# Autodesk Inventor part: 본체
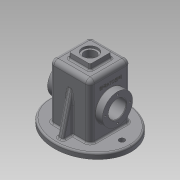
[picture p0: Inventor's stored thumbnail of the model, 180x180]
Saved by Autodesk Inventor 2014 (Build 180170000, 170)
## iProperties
Created: 2017-07
Part Number: 본체
Material: Generic
Document SubType Name: Modeling
Designer: user
Density: 1 g/cm^3
Appearance: Default
Author: user
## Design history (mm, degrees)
sketch "스케치1"
  geometry: 1 further point
sketch "스케치2"
  geometry: 1 further point
sketch "스케치3"
  geometry: 1 further point; 1 other entity
  constraints: 2 other
extrude "돌출1" new body sketch "스케치3" distance "d2" = 10; taper "d3" = 0 deg
sketch "스케치4"
  geometry: L1 (-37, -37)-(37, -37); L2 (37, -37)-(37, 37); L3 (37, 37)-(-37, 37); L4 (-37, 37)-(-37, -37); L5 (-37, -37)-(37, 37); L6 (37, -37)-(-37, 37); 1 further point; 1 other entity
  constraints: 12 end point, 2 midpoint, 2 parallel, 1 horizontal, 1 perpendicular, 1 other
  dimensions: "d4" = 74 distance of L3.end L2.end; "d5" = 74 distance of L2.end L1.end
extrude "돌출2" join sketch "스케치4" distance "d6" = 100; taper "d7" = 0 deg
fillet "모깎기1" dims "d8" = 8
fillet "모깎기2" dims "d9" = 8
sketch "스케치5"
  geometry: L1 (-32, -32)-(32, -32); L2 (32, -32)-(32, 32); L3 (32, 32)-(-32, 32); L4 (-32, 32)-(-32, -32); L5 (-32, -32)-(32, 32); L6 (32, -32)-(-32, 32); 1 further point; 1 other entity
  constraints: 12 end point, 2 midpoint, 2 parallel, 1 horizontal, 1 perpendicular, 1 other
  dimensions: "d10" = 64 distance of L3.end L2.end; "d11" = 64 distance of L2.end L1.end
extrude "돌출3" cut sketch "스케치5" distance "d12" = 105; taper "d13" = 0 deg
sketch "스케치6"
  geometry: L1 (-32, 0)-(32, 0) reference; L2 (-32, 0)-(-32, 105) reference; L3 (-32, 105)-(32, 105) reference; L4 (32, 0)-(32, 105) reference; L5 (75, 10)-(-75, 10) reference; L6 (-75, 0)-(75, 0) reference; L7 (-37, 102)-(-29, 102) reference; L8 (-37, 102)-(-37, 10) reference; L9 (-37, 10)-(-29, 10) reference; L10 (-29, 10)-(-29, 102) reference; L11 (-29, 110)-(-29, 102) reference; L12 (-29, 102)-(29, 102) reference; L13 (29, 102)-(29, 110) reference; L14 (29, 110)-(-29, 110) reference; L15 (29, 102)-(37, 102) reference; L16 (29, 102)-(29, 10) reference; L17 (29, 10)-(37, 10) reference; L18 (37, 10)-(37, 102) reference; L19 (-37, 10)-(-37, 55); L20 (-37, 82.5)-(-50, 82.5); L21 (-50, 82.5)-(-50, 71); L22 (-50, 71)-(-25, 71); L23 (-37, 82.5)-(-32, 82.5); L24 (-37, 55)-(-37, 71); L25 (-32, 82.5)-(-17, 82.5); L26 (-25, 71)-(-25, 75.5); L27 (-25, 75.5)-(-32, 82.5); L28 (-32, 0)-(-32, 105) reference; L29 (-37, 55)-(-17, 55); L30 (-37, 102)-(-37, 10) reference; L31 (-25, 71)-(-25, 75.5); L32 (-32, 82.5)-(-25, 75.5); L33 (-32, 82.5)-(-50, 82.5); L34 (-50, 82.5)-(-50, 71); L35 (-50, 71)-(-25, 71); 1 further point
  constraints: 30 end point, 6 perpendicular, 4 collinear, 4 point on line, 1 horizontal
  node "투영된 루프1"
  node "투영된 루프2"
  node "투영된 루프3"
  node "투영된 루프4"
  node "투영된 루프5"
revolve "회전1" stored, may be unused: angle "d22" = 90 deg
fillet "모깎기3" dims "d23" = 0.5
sketch "스케치7"
  geometry: C1 r 16 at (0, 0) reference; C2 r 16 at (0, 0) reference; 1 further point
extrude "돌출4" cut sketch "스케치7" distance "d24" = 20; taper "d25" = 0 deg
sketch "스케치8"
  geometry: L1 (0, 0)-(-22.5, 0); C1 r 27.5 at (0, 0) reference; 1 further point
  constraints: 2 end point, 1 horizontal
  dimensions: "d26" = 22.5 distance of L1.start L1.end
hole "구멍1" sketch "스케치8" at (-22.5, 0) diameter "d27" = 3.242; stored, may be unused: countersink angle "d31" = 90 deg, drill point angle "d33" = 118 deg; dims "d28" = 8, "d29" = 4, "d30" = 2, "d32" = 10
fillet "모깎기4" dims "d37" = 3
fillet "모깎기5" dims "d38" = 3
chamfer "모따기1" distance "d39" = 1; stored, may be unused: second distance "d40" = 2, angle "d41" = 45 deg
sketch "스케치9"
  geometry: C1 r 16 at (0, 0) reference; C2 r 16 at (0, 0) reference; 1 further point
extrude "돌출5" cut sketch "스케치9" distance "d42" = 20; taper "d43" = 0 deg
revolve "회전2" stored, may be unused: angle "d44" = 90 deg
sketch "스케치10"
  geometry: L1 (0, 0)-(-22.472, 0); C1 r 27.5 at (0, 0) reference; 1 further point
  constraints: 2 end point, 1 horizontal
hole "구멍2" sketch "스케치10" at (-22.472, 0) diameter "d46" = 3.242; stored, may be unused: countersink angle "d50" = 90 deg, drill point angle "d52" = 118 deg; dims "d47" = 8, "d48" = 4, "d49" = 2, "d51" = 10
fillet "모깎기6" dims "d56" = 0.5
fillet "모깎기7" dims "d57" = 0.5
fillet "모깎기8" dims "d58" = 3
fillet "모깎기9" dims "d59" = 3
sketch "스케치11"
  geometry: L1 (-20, -20)-(20, -20); L2 (20, -20)-(20, 20); L3 (20, 20)-(-20, 20); L4 (-20, 20)-(-20, -20); L5 (-20, -20)-(20, 20); L6 (20, -20)-(-20, 20); 1 further point
  constraints: 12 end point, 2 midpoint, 2 parallel, 1 horizontal, 1 perpendicular
  dimensions: "d60" = 40 distance of L3.end L2.end; "d61" = 40 distance of L2.end L1.end
extrude "돌출6" join sketch "스케치11" distance "d62" = 10; taper "d63" = -5 deg
fillet "모깎기10" dims "d64" = 3
fillet "모깎기11" dims "d65" = 3
sketch "스케치12"
  geometry: 1 further point
hole "구멍3" sketch "스케치12" at (0, 0) diameter "d66" = 21; stored, may be unused: countersink angle "d70" = 90 deg, drill point angle "d72" = 0 deg; dims "d67" = 8, "d68" = 28, "d69" = 4, "d71" = 20
sketch "스케치13"
  geometry: L1 (0, 0)-(58, 0); C1 r 5 at (58, 0); 1 other entity
  constraints: 2 end point, 1 centre point, 1 coincident, 1 horizontal, 1 other
  dimensions: "d73" = 58 distance of L1.start L1.end; "d74" = 10 diameter of C1
extrude "돌출7" cut sketch "스케치13" stored distance "d75" = 10; taper "d76" = 0 deg
fillet "모깎기12" dims "d77" = 3
sketch "스케치14"
  geometry: L1 (-37, 10)-(-37, 102) reference; L2 (-29, 102)-(-37, 102) reference; L3 (-29, 102)-(-29, 10) reference; L4 (-29, 10)-(-37, 10) reference; L5 (-37, 10)-(-37, 102) reference; L6 (29, 105)-(10.5, 105) reference; L7 (10.5, 105)-(10.5, 116) reference; L8 (10.5, 116)-(14, 116) reference; L9 (14, 116)-(14, 120) reference; L10 (14, 120)-(19.125, 120) reference; L11 (19.125, 120)-(19.76, 112.739) reference; L12 (22.749, 110)-(29, 110) reference; L13 (37, 102)-(37, 10) reference; L14 (37, 10)-(62, 10) reference; L15 (65, 7)-(65, 0) reference; L16 (65, 0)-(32, 0) reference; L17 (32, 0)-(32, 102) reference; L18 (-32, 102)-(-32, 0) reference; L19 (-32, 0)-(-65, 0) reference; L20 (-65, 0)-(-65, 7) reference; L21 (-62, 10)-(-37, 10) reference; L22 (-37, 10)-(-37, 102) reference; L23 (-29, 110)-(-22.749, 110) reference; L24 (-19.76, 112.739)-(-19.125, 120) reference; L25 (-19.125, 120)-(-14, 120) reference; L26 (-14, 120)-(-14, 116) reference; L27 (-14, 116)-(-10.5, 116) reference; L28 (-10.5, 116)-(-10.5, 105) reference; L29 (-10.5, 105)-(-29, 105) reference; L30 (-55, 10)-(-37, 82.194); L31 (-55, 10)-(-37, 10); L32 (-37, 10)-(-37, 82.194); L33 (-37, 82.194)-(-55, 10); A1 r 3 centre (29, 102) between (32, 102) and (29, 105) reference; A2 r 3 centre (22.749, 113) between (19.76, 112.739) and (22.749, 110) reference; A3 r 8 centre (29, 102) between (37, 102) and (29, 110) reference; A4 r 3 centre (-29, 102) between (-29, 105) and (-32, 102) reference; A5 r 8 centre (-29, 102) between (-29, 110) and (-37, 102) reference; A6 r 3 centre (-22.749, 113) between (-22.749, 110) and (-19.76, 112.739) reference; 1 further point
  constraints: 8 end point, 2 collinear, 2 point on line, 1 parallel, 1 vertical alignment, 2 other
  dimensions: "d79" = 14 deg angle of L20 L30
extrude "돌출8" join sketch "스케치14" stored distance "d80" = 10; taper "d81" = 0 deg
fillet "모깎기13" dims "d82" = 3
fillet "모깎기14" dims "d83" = 3
sketch "스케치15"
  geometry: L1 (0, 0)-(10, 0) reference; L2 (10, 92)-(10, 0) reference; L3 (10, 0)-(0, 0) reference; L4 (0, 0)-(0, 92) reference; L5 (0, 92)-(10, 92) reference; L6 (37, 0)-(37, 102) reference; L7 (37, 102)-(72.122, 102) reference; L8 (72.122, 102)-(72.122, 95) reference; L9 (68.631, 92)-(42, 92) reference; L10 (42, 92)-(42, 0) reference; L11 (34, -8)-(-24, -8) reference; L12 (-32, 0)-(-32, 92) reference; L13 (-32, 92)-(-58.631, 92) reference; L14 (-62.122, 95)-(-62.122, 102) reference; L15 (-62.122, 102)-(-27, 102) reference; L16 (-27, 102)-(-27, 0) reference; L17 (-24, -3)-(34, -3) reference; A1 r 3 centre (34, 0) between (34, -3) and (37, 0) reference; A2 r 8 centre (34, 0) between (34, -8) and (42, 0) reference; A3 r 8 centre (-24, 0) between (-32, 0) and (-24, -8) reference; A4 r 3 centre (-24, 0) between (-27, 0) and (-24, -3) reference; 1 further point
  constraints: 2 other
extrude "돌출9" cut sketch "스케치15" stored distance "d84" = 10; taper "d85" = 0 deg
fillet "모깎기15" dims "d86" = 3
fillet "모깎기16" dims "d87" = 3
fillet "모깎기17" dims "d88" = 3
chamfer "모따기2" distance "d89" = 1; stored, may be unused: second distance "d90" = 2, angle "d91" = 45 deg
node "작업 평면1"
sketch "스케치16"
  geometry: L1 (89, 66)-(0, 66) reference; L2 (-18, 45.137)-(-18, 12.863) reference; 2 further points
  constraints: 1 other
  dimensions: "d93" = 37 distance from line of L1 point (12, 29); "d94" = 30 distance from line of L2 point (12, 29)
feature "엠보싱1" sketch "스케치16" dims "d95" = 0.5, "d96" = 0
sketch "스케치17"
  geometry: L1 (0, 0)-(10, 0) reference; L2 (0, 0)-(0, -92) reference; L3 (0, -92)-(10, -92) reference; L4 (10, -92)-(10, 0) reference; 1 further point
extrude "돌출10" cut sketch "스케치17" stored distance "d97" = 10; taper "d98" = 0 deg
node "솔리드1"
pattern_circular "원형 패턴1" dims angle "d35" = 360 deg
mirror "대칭1"
pattern_circular "원형 패턴2" dims angle "d54" = 360 deg
mirror "대칭2"
mirror "대칭3"
node "투영된 루프6"
node "투영된 루프7"
node "투영된 루프8"
node "절단 모서리 투영1"
node "절단 모서리 투영2"
other parameters: "d92" = 7
